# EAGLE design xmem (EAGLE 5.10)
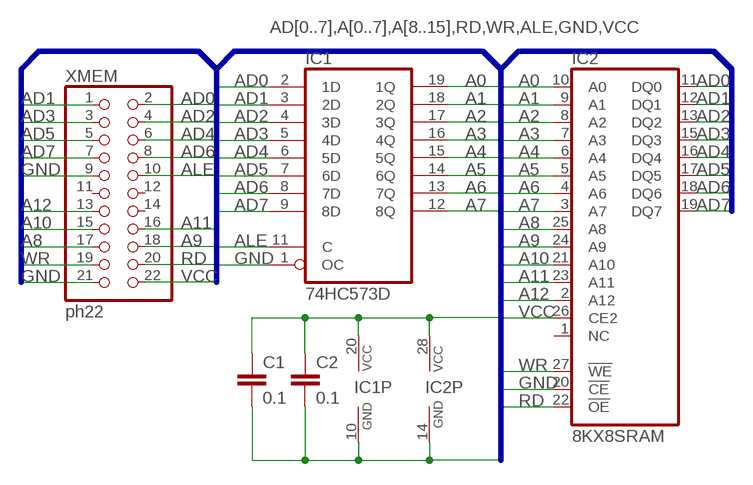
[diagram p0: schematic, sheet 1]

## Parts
C1  0.1  C-EUC0805K  [C0805K]
C2  0.1  C-EUC0805K  [C0805K]
IC1  74HC573D  [SO20W]
IC2  8KX8SRAM  [SOP28_SRAM64K]
XMEM  ph22  PINHD-2X11  [2X11]

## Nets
A0: IC1.19(1Q) IC2.10(A0)
A1: IC1.18(2Q) IC2.9(A1)
A2: IC1.17(3Q) IC2.8(A2)
A3: IC1.16(4Q) IC2.7(A3)
A4: IC1.15(5Q) IC2.6(A4)
A5: IC1.14(6Q) IC2.5(A5)
A6: IC1.13(7Q) IC2.4(A6)
A7: IC1.12(8Q) IC2.3(A7)
A8: IC2.25(A8) XMEM.17
A9: IC2.24(A9) XMEM.18
A10: IC2.21(A10) XMEM.15
A11: IC2.23(A11) XMEM.16
A12: IC2.2(A12) XMEM.13
AD0: IC1.2(1D) IC2.11(DQ0) XMEM.2
AD1: IC1.3(2D) IC2.12(DQ1) XMEM.1
AD2: IC1.4(3D) IC2.13(DQ2) XMEM.4
AD3: IC1.5(4D) IC2.15(DQ3) XMEM.3
AD4: IC1.6(5D) IC2.16(DQ4) XMEM.6
AD5: IC1.7(6D) IC2.17(DQ5) XMEM.5
AD6: IC1.8(7D) IC2.18(DQ6) XMEM.8
AD7: IC1.9(8D) IC2.19(DQ7) XMEM.7
ALE: IC1.11(C) XMEM.10
GND: C1.2 C2.2 IC1.1(OC) IC1.10(GND) IC2.14(GND) IC2.20(!CE) XMEM.9 XMEM.21
RD: IC2.22(!OE) XMEM.20
VCC: C1.1 C2.1 IC1.20(VCC) IC2.26(CE2) IC2.28(VCC) XMEM.22
WR: IC2.27(!WE) XMEM.19
Unconnected: IC2.1(NC) XMEM.11 XMEM.12 XMEM.14

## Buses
AD[0..7],A[0..7],A[8..15],RD,WR,ALE,GND,VCC

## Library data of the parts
C1 C2 = rcl:C-EU: CAPACITOR, European symbol
IC1 = 74xx-eu:74*573: 8-bit D latch BUS DRIVER
IC2 = eagle_cglib:8KX8SRAM
XMEM = pinhead:PINHD-2X11: PIN HEADER

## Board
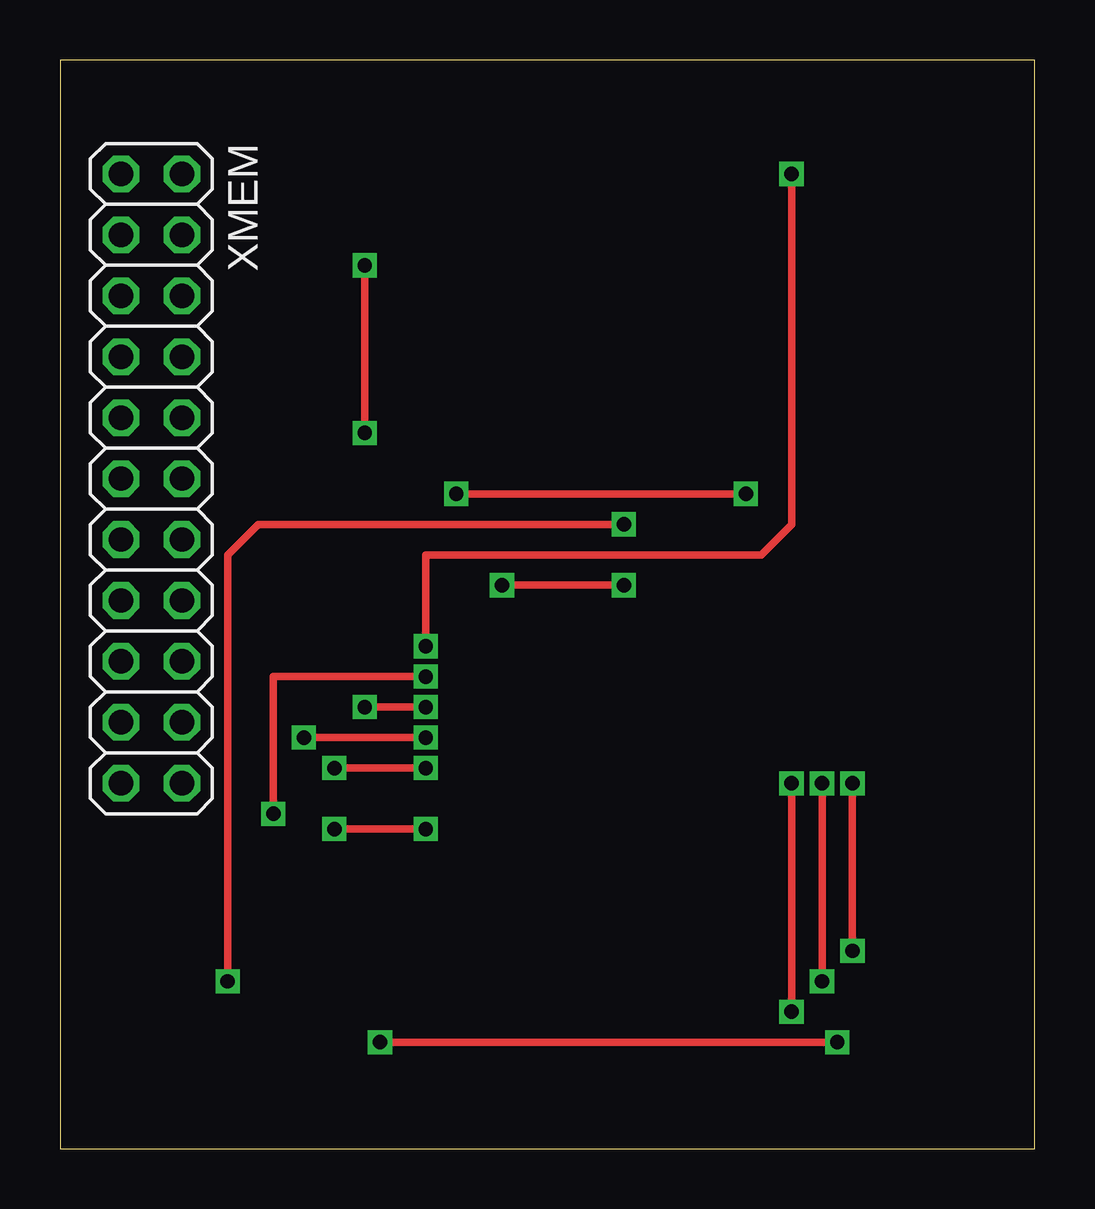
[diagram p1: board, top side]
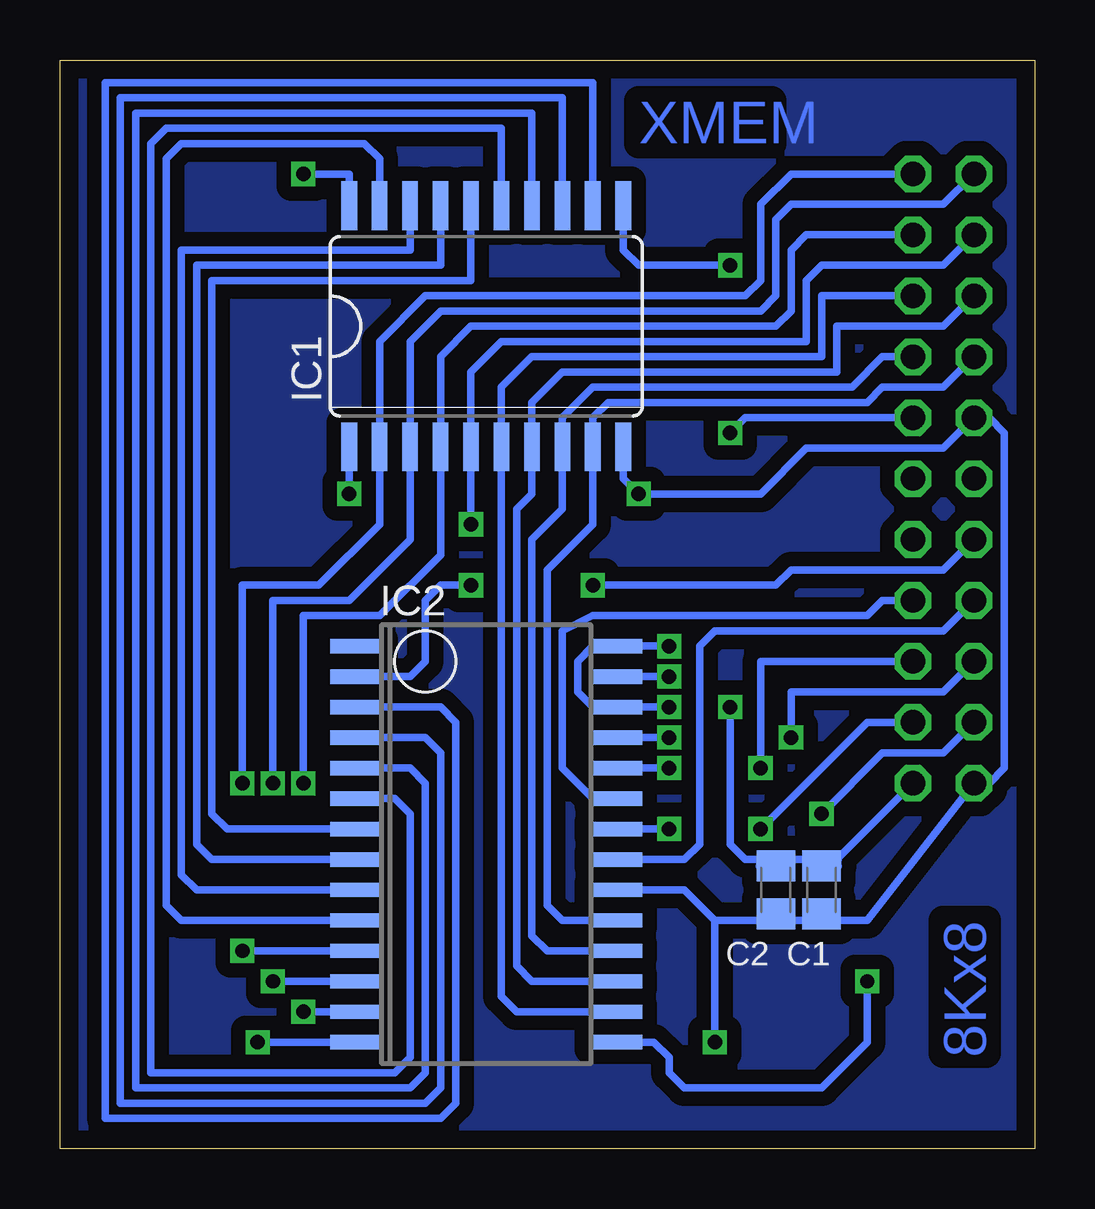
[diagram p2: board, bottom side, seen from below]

Size 40.62 x 45.39 mm. Coordinates in mm from the lower left corner, seen from the top.
Outline: 0,0 40.62,0 40.62,45.39 0,45.39 0,0
Copper layers (1*16): Top 0.035mm / dielectric 1.5mm / Bottom 0.035mm
Design rules "default *": minimum track width 10mil, minimum drill 15mil, track to track 8mil, track to pad 8mil, pad to pad 8mil, via to via 8mil, smd to smd 8mil, copper to edge 30mil, drill to drill 8mil, minimum pad ring 10mil, minimum via ring 8mil, stop-mask expansion 4mil, vias tented up to drill 0mil, thermal gap 10mil

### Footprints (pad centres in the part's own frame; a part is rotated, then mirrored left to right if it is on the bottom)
C0805K = smd 1.3 x 1.6: 1 -1,0; 2 1,0
SO20W = smd 0.66 x 2.032: 1 -5.715,-5.029; 2 -4.445,-5.029; 3 -3.175,-5.029; 4 -1.905,-5.029; 5 -0.635,-5.029; 6 0.635,-5.029; 7 1.905,-5.029; 8 3.175,-5.029; 9 4.445,-5.029; 10 5.715,-5.029; 11 5.715,5.029; 12 4.445,5.029; 13 3.175,5.029; 14 1.905,5.029; 15 0.635,5.029; 16 -0.635,5.029; 17 -1.905,5.029; 18 -3.175,5.029; 19 -4.445,5.029; 20 -5.715,5.029
SOP28_SRAM64K = smd 0.6 x 2.2: 1 -10.795,-2.86; 2 -9.525,-2.86; 3 -8.255,-2.86; 4 -6.985,-2.86; 5 -5.715,-2.86; 6 -4.445,-2.86; 7 -3.175,-2.86; 8 -1.905,-2.86; 9 -0.635,-2.86; 10 0.635,-2.86; 11 1.905,-2.86; 12 3.175,-2.86; 13 4.445,-2.86; 14 5.715,-2.86; 15 5.715,7.94; 16 4.445,7.94; 17 3.175,7.94; 18 1.905,7.94; 19 0.635,7.94; 20 -0.635,7.94; 21 -1.905,7.94; 22 -3.175,7.94; 23 -4.445,7.94; 24 -5.715,7.94; 25 -6.985,7.94; 26 -8.255,7.94; 27 -9.525,7.94; 28 -10.795,7.94
2X11 = drill 1.016 octagon: 1 -12.7,-1.27; 2 -12.7,1.27; 3 -10.16,-1.27; 4 -10.16,1.27; 5 -7.62,-1.27; 6 -7.62,1.27; 7 -5.08,-1.27; 8 -5.08,1.27; 9 -2.54,-1.27; 10 -2.54,1.27; 11 0,-1.27; 12 0,1.27; 13 2.54,-1.27; 14 2.54,1.27; 15 5.08,-1.27; 16 5.08,1.27; 17 7.62,-1.27; 18 7.62,1.27; 19 10.16,-1.27; 20 10.16,1.27; 21 12.7,-1.27; 22 12.7,1.27

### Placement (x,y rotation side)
C1  8.89,10.79 270 bottom
C2  10.79,10.79 270 bottom
IC1  22.86,34.29 0 bottom
IC2  25.4,10.16 270 bottom
XMEM  3.81,27.94 270 top

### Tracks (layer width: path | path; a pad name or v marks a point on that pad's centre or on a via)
A0
  Bottom 0.305: IC1.19 27.3,41.27 27.94,41.91 35.56,41.91 36.2,41.27 36.2,10.16 35.56,9.53 IC2.10
A1
  Bottom 0.305: 26.04,39.37 IC1.18 26.04,37.47 35.56,37.47 35.56,11.43 34.92,10.79 IC2.9
A2
  Bottom 0.305: IC1.17 24.77,36.83 34.92,36.83 34.92,12.7 34.29,12.06 IC2.8
A3
  Bottom 0.305: IC1.16 23.5,36.2 34.29,36.2 34.29,13.97 33.66,13.34 IC2.7
A4
  Bottom 0.305: IC1.15 22.23,42.55 36.2,42.55 36.83,41.91 36.83,3.17 26.67,3.17 26.04,3.81 26.04,13.97 26.67,14.61 IC2.6
A5
  Bottom 0.305: IC1.14 20.95,43.18 37.47,43.18 37.47,2.54 26.04,2.54 25.4,3.17 25.4,15.24 26.04,15.88 IC2.5
A6
  Bottom 0.305: IC1.13 19.68,43.81 38.1,43.81 38.1,1.91 25.4,1.91 24.77,2.54 24.77,16.51 25.4,17.14 IC2.4
A7
  Bottom 0.305: IC1.12 18.41,44.45 38.73,44.45 38.73,1.27 24.77,1.27 24.13,1.91 24.13,17.78 24.77,18.41 IC2.3
A8  (via drill 0.6)
  Top 0.305: v10.16,17.14 v15.24,17.14
  Bottom 0.305: v10.16,17.14 10.16,19.05 3.81,19.05 XMEM.17 | v15.24,17.14 IC2.25
A9  (via drill 0.6)
  Top 0.305: v11.43,15.88 v15.24,15.88
  Bottom 0.305: XMEM.18 11.43,20.32 v11.43,15.88 | v15.24,15.88 IC2.24
A10
  Bottom 0.305: IC2.21 14.61,12.06 13.97,12.7 13.97,20.95 13.34,21.59 3.81,21.59 XMEM.15
A11
  Bottom 0.305: IC2.23 18.41,14.61 19.68,15.88 19.68,21.59 18.41,22.23 6.99,22.23 6.35,22.86 XMEM.16
A12  (via drill 0.6)
  Top 0.305: v18.41,23.5 v23.5,23.5
  Bottom 0.305: v23.5,23.5 24.77,23.5 25.4,22.86 25.4,20.32 26.04,19.68 IC2.2 | XMEM.13 3.81,24.13 10.16,24.13 10.79,23.5 v18.41,23.5
AD0  (via drill 0.6)
  Top 0.305: v33.02,8.26 v33.02,15.24
  Bottom 0.305: v33.02,15.24 33.02,23.5 29.84,23.5 27.3,26.04 IC1.2 27.3,33.66 25.4,35.56 12.06,35.56 11.43,36.2 11.43,39.37 10.16,40.64 XMEM.2 | IC2.11 v33.02,8.26
AD1  (via drill 0.6)
  Top 0.305: v31.75,6.99 v31.75,15.24
  Bottom 0.305: v31.75,15.24 31.75,22.86 28.57,22.86 26.04,25.4 IC1.3 26.04,33.66 24.77,34.92 11.43,34.92 10.79,35.56 10.79,38.73 10.16,39.37 3.81,39.37 XMEM.1 | IC2.12 v31.75,6.99
AD2  (via drill 0.6)
  Top 0.305: v30.48,5.71 v30.48,15.24
  Bottom 0.305: v30.48,15.24 30.48,22.23 27.3,22.23 24.77,24.77 IC1.4 24.77,33.02 23.5,34.29 10.79,34.29 10.16,34.92 10.16,37.47 9.53,38.1 XMEM.4 | IC2.13 v30.48,5.71
AD3  (via drill 0.6)
  Top 0.305: v6.99,6.99 6.99,24.77 8.26,26.04 v23.5,26.04
  Bottom 0.305: IC2.15 15.88,4.45 15.24,3.81 15.24,3.17 14.61,2.54 8.89,2.54 6.99,4.45 v6.99,6.99 | v23.5,26.04 IC1.5 23.5,32.38 22.23,33.66 9.53,33.66 9.53,36.2 8.89,36.83 3.81,36.83 XMEM.3
AD4
  Bottom 0.305: IC2.16 21.59,5.71 22.23,6.35 IC1.6 22.23,31.75 20.95,33.02 8.89,33.02 8.89,35.56 XMEM.6
AD5
  Bottom 0.305: IC2.17 20.95,6.99 21.59,7.62 21.59,26.67 20.95,27.3 IC1.7 20.95,31.11 19.68,32.38 8.26,32.38 8.26,34.29 3.81,34.29 XMEM.5
AD6
  Bottom 0.305: IC2.18 20.32,8.26 20.95,8.89 20.95,25.4 19.68,26.67 IC1.8 19.68,30.48 18.41,31.75 7.62,31.75 6.35,33.02 XMEM.8
AD7
  Bottom 0.305: IC2.19 19.68,9.53 20.32,10.16 20.32,24.13 18.41,26.04 IC1.9 18.41,30.48 17.78,31.11 6.99,31.11 6.35,31.75 3.81,31.75 XMEM.7
ALE  (via drill 0.6)
  Top 0.305: v12.7,29.84 v12.7,36.83
  Bottom 0.305: XMEM.10 12.06,30.48 v12.7,29.84 | IC1.11 17.14,37.47 16.51,36.83 v12.7,36.83
GND  (via drill 0.6)
  Top 0.305: v13.34,4.45 v32.38,4.45 | v16.51,27.3 v28.57,27.3
  Bottom 0.305: 13.34,9.53 10.79,9.53 8.89,9.53 6.99,9.53 XMEM.21 1.91,15.24 1.27,15.88 1.27,29.84 1.91,30.48 XMEM.9 3.81,29.21 9.53,29.21 11.43,27.3 v16.51,27.3 17.14,27.94 IC1.10 | 13.34,9.53 14.61,10.79 IC2.20 | v32.38,4.45 IC2.14 | 13.34,9.53 v13.34,4.45 | v28.57,27.3 IC1.1
  Bottom 0.406: 8.89,9.53 C1.2 | 10.79,9.53 C2.2
N$1
  pour Bottom (isolate 0.61): 0,45.09 40.64,45.09 40.64,0 0,0
RD  (via drill 0.6)
  Top 0.305: v11.43,13.34 v15.24,13.34
  Bottom 0.305: XMEM.20 6.99,17.78 v11.43,13.34 | v15.24,13.34 IC2.22
VCC  (via drill 0.6)
  Top 0.305: v12.7,18.41 v15.24,18.41 | v15.24,20.95 15.24,24.77 29.21,24.77 30.48,26.04 v30.48,40.64
  Bottom 0.305: XMEM.22 8.26,12.06 11.43,12.06 12.06,12.06 12.7,12.7 v12.7,18.41 | v15.24,18.41 IC2.26 18.41,18.41 19.05,19.05 19.05,20.32 18.41,20.95 IC2.28 v15.24,20.95 | v30.48,40.64 28.57,40.64 IC1.20
  Bottom 0.406: C1.1 8.26,11.79 8.26,12.06 | C2.1 11.43,11.79 11.43,12.06
WR  (via drill 0.6)
  Top 0.305: v8.89,13.97 8.89,19.68 v15.24,19.68
  Bottom 0.305: XMEM.19 3.81,16.51 6.35,16.51 v8.89,13.97 | v15.24,19.68 IC2.27

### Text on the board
Bottom: XMEM | 8Kx8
